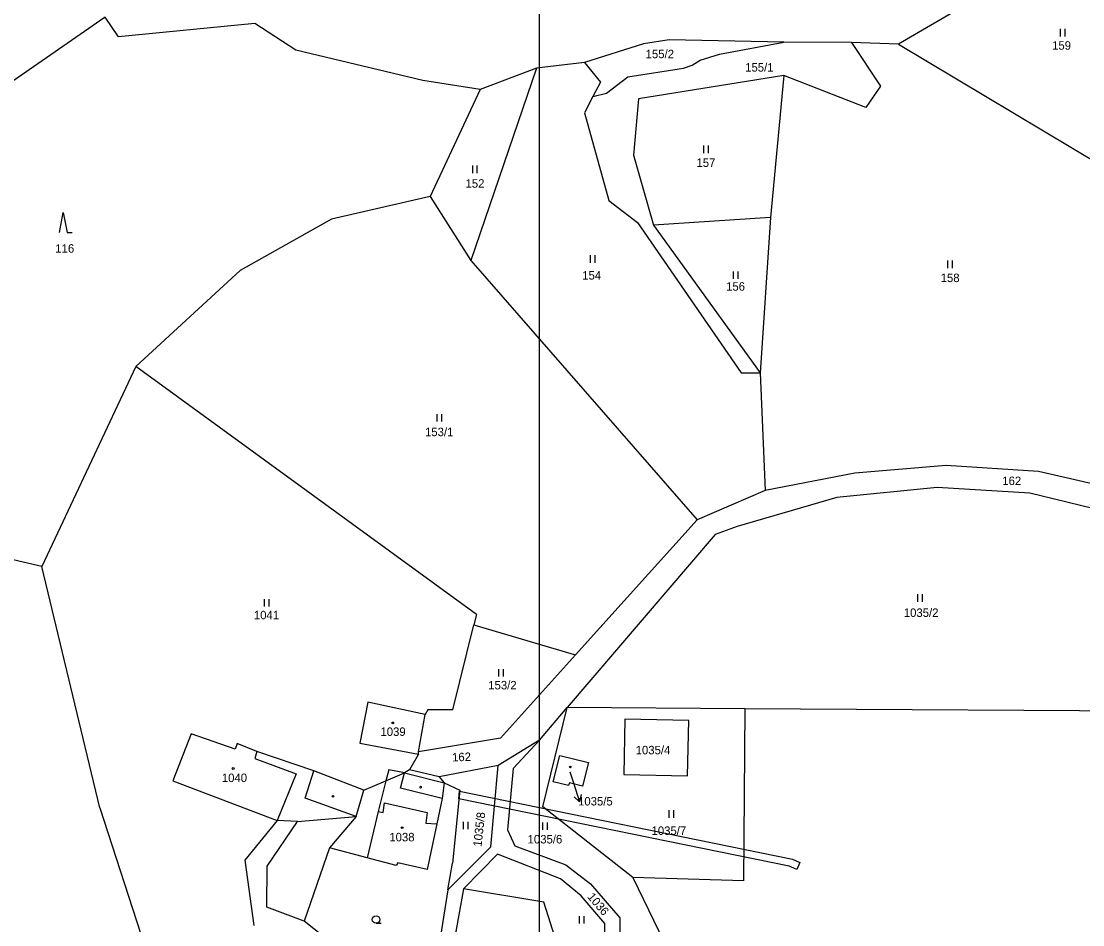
# Model space of a CAD drawing. Extents: x -670359 to -660124, y -978807 to -970072.
# Drawn here: x -670103.9 to -669891.1, y -977465.8 to -977284.7 of the extents above; entities that cross this region are included whole.
import ezdxf

# ---------------------------------------------------------------- set-up
doc = ezdxf.new("R2010")
doc.units = 0
for name, color, linetype in [('Hranice parcel', 7, 'Continuous'), ('ML1000', 7, 'Continuous'), ('Parcelní čísla', 7, 'Continuous'), ('Vnitřní kresba', 7, 'Continuous'), ('Věcná břemena k části', 7, 'Continuous'), ('Značky budov', 7, 'Continuous'), ('Značky kultur', 7, 'Continuous')]:
    doc.layers.add(name, color=color, linetype=linetype)

msp = doc.modelspace()

# ---------------------------------------------------------------- linework, layer by layer
at = {"layer": 'Hranice parcel'}
for p, q in [((-670000.01, -977428.74), (-670005.31, -977434.42)), ((-670009.75, -977450.12), (-670008.29, -977433.88)), ((-670005.31, -977434.42), (-670006.43, -977446.74)), ((-670088.14, -977442.36), (-670079.11, -977470.1)), ((-670006.43, -977446.74), (-670004.98, -977449.96)), ((-670018.36, -977458.79), (-670009.75, -977450.12)), ((-670004.98, -977449.96), (-669994.72, -977453.76)), ((-670008.41, -977451.61), (-670015.27, -977458.55)), ((-669995.83, -977456.55), (-670008.41, -977451.61)), ((-670018.36, -977458.79), (-670017.48, -977453.41)), ((-669994.72, -977453.76), (-669989.76, -977457.53)), ((-669991.65, -977459.94), (-669995.83, -977456.55)), ((-670018.36, -977458.79), (-670022.83, -977486.05)), ((-669989.76, -977457.53), (-669983.91, -977464.41)), ((-669986.93, -977465.5), (-669991.65, -977459.94)), ((-669987.06, -977474.79), (-669986.93, -977465.5)), ((-669983.91, -977464.41), (-669984.06, -977475.2))]:
    msp.add_line(p, q, dxfattribs=at)
for points in [[(-669899.87, -977272.82), (-669928.04, -977289.3)], [(-670087.08, -977283.85), (-670131.79, -977314.81)], [(-670084.43, -977287.79), (-670087.08, -977283.85)], [(-670057.09, -977285.13), (-670084.43, -977287.79)], [(-670048.87, -977290.52), (-670057.09, -977285.13)], [(-669989.31, -977299.81), (-669986.59, -977299.13), (-669982.28, -977295.87), (-669971.16, -977294.1), (-669969.41, -977293.48), (-669967.78, -977292.5), (-669963.95, -977291.28), (-669951.02, -977288.89)], [(-669974.03, -977288.45), (-669979.14, -977289.2)], [(-669951.02, -977288.89), (-669974.03, -977288.45)], [(-669937.48, -977288.95), (-669951.02, -977288.89)], [(-669937.48, -977288.95), (-669931.67, -977297.71)], [(-669928.04, -977289.3), (-669937.48, -977288.95)], [(-670023.39, -977296.58), (-670048.87, -977290.52)], [(-669979.14, -977289.2), (-669991.01, -977292.98)], [(-669928.04, -977289.3), (-669881.51, -977317.07)], [(-669991.01, -977292.98), (-670000.63, -977294.13)], [(-669991.01, -977292.98), (-669987.82, -977296.93)], [(-670000.63, -977294.13), (-670013.78, -977332.64)], [(-670000.63, -977294.13), (-670011.94, -977298.38)], [(-670011.94, -977298.38), (-670023.39, -977296.58)], [(-669987.82, -977296.93), (-669989.31, -977299.81)], [(-669951.04, -977295.59), (-669980.2, -977300.24)], [(-669951.04, -977295.59), (-669953.68, -977324.05)], [(-669934.61, -977301.96), (-669951.04, -977295.59)], [(-670011.94, -977298.38), (-670021.92, -977319.82)], [(-669931.67, -977297.71), (-669934.61, -977301.96)], [(-669989.31, -977299.81), (-669990.98, -977303.02)], [(-669980.2, -977300.24), (-669981.18, -977311.51)], [(-669990.98, -977303.02), (-669986.09, -977320.65)], [(-669981.18, -977311.51), (-669977.19, -977325.55)], [(-670021.92, -977319.82), (-670041.73, -977324.34)], [(-670021.92, -977319.82), (-670013.78, -977332.64)], [(-669986.09, -977320.65), (-669980.39, -977325.01)], [(-670041.73, -977324.34), (-670059.99, -977334.68)], [(-669980.39, -977325.01), (-669959.59, -977355.17)], [(-669953.68, -977324.05), (-669977.19, -977325.55)], [(-669953.68, -977324.05), (-669955.76, -977355.15)], [(-669977.19, -977325.55), (-669955.76, -977355.15)], [(-670013.78, -977332.64), (-669968.39, -977384.63)], [(-670059.99, -977334.68), (-670080.94, -977353.88)], [(-670080.94, -977353.88), (-670099.79, -977393.97)], [(-670012.64, -977403.62), (-670080.94, -977353.88)], [(-669959.59, -977355.17), (-669955.76, -977355.15)], [(-669955.76, -977355.15), (-669954.75, -977378.72)], [(-669918.47, -977373.71), (-669936.77, -977375.26)], [(-669899.99, -977374.96), (-669918.47, -977373.71)], [(-669936.77, -977375.26), (-669954.75, -977378.72)], [(-669884.54, -977378.46), (-669899.99, -977374.96)], [(-669920.28, -977378.11), (-669940.43, -977380.15)], [(-669901.73, -977379.28), (-669920.28, -977378.11)], [(-669954.75, -977378.72), (-669968.39, -977384.63)], [(-669940.43, -977380.15), (-669960.39, -977385.94)], [(-669889.07, -977382.32), (-669901.73, -977379.28)], [(-669968.39, -977384.63), (-669992.8, -977411.69)], [(-669960.39, -977385.94), (-669964.78, -977387.57)], [(-669964.78, -977387.57), (-669994.46, -977422.25)], [(-670099.79, -977393.97), (-670112.18, -977391.09)], [(-670088.14, -977442.36), (-670099.79, -977393.97)], [(-670012.64, -977403.62), (-670013.15, -977405.65)], [(-670017.41, -977422.7), (-670013.15, -977405.65)], [(-670013.15, -977405.65), (-670010.72, -977406.37), (-669993.72, -977411.42), (-669992.8, -977411.69)], [(-670007.85, -977428.37), (-669992.8, -977411.69)], [(-670034.45, -977421.14), (-670036.03, -977429.37)], [(-670022.94, -977423.62), (-670034.45, -977421.14)], [(-670022.38, -977422.67), (-670022.94, -977423.62)], [(-670017.41, -977422.7), (-670022.38, -977422.67)], [(-670000.01, -977428.74), (-669994.46, -977422.25)], [(-669981.31, -977456.31), (-669999.34, -977442.1), (-669994.46, -977422.25)], [(-669958.87, -977422.47), (-669994.46, -977422.25)], [(-669958.87, -977422.47), (-669959.15, -977456.98), (-669981.31, -977456.31)], [(-669869.36, -977423.01), (-669958.87, -977422.47)], [(-670024.28, -977431.13), (-670022.94, -977423.62)], [(-669982.9, -977424.54), (-669983.13, -977435.67)], [(-669970.1, -977424.8), (-669982.9, -977424.54)], [(-669970.33, -977435.94), (-669970.1, -977424.8)], [(-670069.87, -977427.53), (-670073.53, -977436.95)], [(-670061, -977430.56), (-670069.87, -977427.53)], [(-670060.6, -977429.44), (-670061, -977430.56)], [(-670056.69, -977431.07), (-670060.6, -977429.44)], [(-670036.03, -977429.37), (-670024.28, -977431.61)], [(-670007.85, -977428.37), (-670024.28, -977431.13)], [(-670000.01, -977428.74), (-670008.29, -977433.88)], [(-670045.27, -977434.9), (-670056.69, -977431.07)], [(-670024.28, -977431.61), (-670026.06, -977434.72)], [(-670024.28, -977431.61), (-670024.28, -977431.13)], [(-669997.28, -977437.1), (-669995.94, -977431.82)], [(-669995.94, -977431.82), (-669990.21, -977433.27)], [(-669990.21, -977433.27), (-669991.41, -977437.97)], [(-670035.22, -977438.81), (-670045.27, -977434.9)], [(-670030.25, -977434.7), (-670030.81, -977436.93)], [(-670027.11, -977435.35), (-670030.25, -977434.7)], [(-670026.06, -977434.72), (-670027.11, -977435.35)], [(-670020.15, -977436.12), (-670026.06, -977434.72)], [(-670008.29, -977433.88), (-670020.15, -977436.12)], [(-669983.13, -977435.67), (-669970.33, -977435.94)], [(-670073.53, -977436.95), (-670052.62, -977444.85)], [(-670030.81, -977436.93), (-670032.37, -977443.07)], [(-670020.15, -977436.12), (-670019.12, -977437.33)], [(-670019.12, -977437.33), (-670019.54, -977440.44)], [(-670019.12, -977437.33), (-670016.01, -977438.79)], [(-669994.18, -977437.89), (-669997.28, -977437.1)], [(-669994.03, -977437.31), (-669994.18, -977437.89)], [(-669991.41, -977437.97), (-669994.03, -977437.31)], [(-670036.77, -977444.08), (-670035.22, -977438.81)], [(-670016.01, -977438.79), (-670017.48, -977453.41)], [(-670019.54, -977440.44), (-670020.62, -977445.55)], [(-670048.54, -977445.04), (-670036.77, -977444.08)], [(-670032.37, -977443.07), (-670034.59, -977452.33)], [(-670052.62, -977444.85), (-670059.08, -977452.8)], [(-670054.61, -977454.03), (-670048.54, -977445.04)], [(-670048.54, -977445.04), (-670052.62, -977444.85)], [(-670020.62, -977445.55), (-670022.53, -977454.66)], [(-670042.1, -977450.36), (-670047.21, -977465.04)], [(-670034.59, -977452.33), (-670042.1, -977450.36)], [(-670059.08, -977452.8), (-670057.31, -977465.91)], [(-670028.76, -977453.89), (-670034.59, -977452.33)], [(-670054.67, -977462.27), (-670054.61, -977454.03)], [(-670028.44, -977453.34), (-670028.76, -977453.89)], [(-670022.53, -977454.66), (-670028.44, -977453.34)], [(-669981.31, -977456.31), (-669976.1, -977467.06), (-669976.06, -977481.88)], [(-670015.27, -977458.55), (-670020.69, -977488.66)], [(-669999.13, -977461.22), (-670015.27, -977458.55)], [(-669989.82, -977490.72), (-669999.13, -977461.22)], [(-670047.21, -977465.04), (-670054.67, -977462.27)], [(-670037.86, -977472.47), (-670047.21, -977465.04)]]:
    msp.add_lwpolyline(points, dxfattribs=at)
at = {"layer": 'ML1000'}
msp.add_lwpolyline([(-669375, -977000), (-669375, -977500), (-670000, -977500), (-670000, -977000)], close=True, dxfattribs=at)
at = {"layer": 'Parcelní čísla'}
for p, q in [((-669993.91, -977435.1), (-669993.2, -977437.3)), ((-669991.66, -977439.64), (-669991.97, -977441.11))]:
    msp.add_line(p, q, dxfattribs=at)
msp.add_lwpolyline([(-669993.2, -977437.3), (-669991.97, -977441.11), (-669993.09, -977440.1)], dxfattribs=at)
at = {"layer": 'Vnitřní kresba'}
for points in [[(-670056.69, -977431.07), (-670057.1, -977432.42)], [(-670057.1, -977432.42), (-670048.8, -977435.52)], [(-670048.8, -977435.52), (-670052.62, -977444.85)], [(-670046.99, -977440.41), (-670045.27, -977434.9)], [(-670030.81, -977436.93), (-670027.11, -977435.35)], [(-670027.85, -977438.38), (-670027.11, -977435.35)], [(-670027.11, -977435.35), (-670019.12, -977437.33)], [(-670035.22, -977438.81), (-670030.81, -977436.93)], [(-670019.54, -977440.44), (-670027.85, -977438.38)], [(-670036.77, -977444.08), (-670046.99, -977440.41)], [(-670031.33, -977443.24), (-670031.07, -977441.32)], [(-670031.07, -977441.32), (-670022.52, -977443.3)], [(-670036.77, -977444.08), (-670042.1, -977450.36)], [(-670032.37, -977443.07), (-670031.33, -977443.24)], [(-670022.52, -977443.3), (-670022.78, -977445.38)], [(-670022.78, -977445.38), (-670020.62, -977445.55)]]:
    msp.add_lwpolyline(points, dxfattribs=at)
at = {"layer": 'Věcná břemena k části'}
for p, q in [((-670016.18, -977440.52), (-670016.03, -977439.02)), ((-670016.03, -977439.02), (-669949.32, -977452.64)), ((-669949.95, -977454.03), (-670016.18, -977440.52)), ((-669949.32, -977452.64), (-669947.86, -977453.28)), ((-669948.46, -977454.69), (-669949.95, -977454.03)), ((-669947.86, -977453.28), (-669948.46, -977454.69))]:
    msp.add_line(p, q, dxfattribs=at)
at = {"layer": 'Značky budov'}
for centre in [(-670029.44, -977425.32), (-670061.43, -977434.45), (-669993.83, -977434.14), (-670027.55, -977446.3)]:
    msp.add_circle(centre, 0.175, dxfattribs=at)
at = {"layer": 'Značky kultur'}
for p, q in [((-669895.63, -977286.23), (-669895.63, -977287.73)), ((-669894.63, -977287.73), (-669894.63, -977286.23)), ((-669967.17, -977309.63), (-669967.17, -977311.13)), ((-669966.17, -977311.13), (-669966.17, -977309.63)), ((-670013.48, -977313.63), (-670013.48, -977315.13)), ((-670012.48, -977315.13), (-670012.48, -977313.63)), ((-669989.84, -977331.59), (-669989.84, -977333.09)), ((-669988.84, -977333.09), (-669988.84, -977331.59)), ((-669918.24, -977332.67), (-669918.24, -977334.17)), ((-669917.24, -977334.17), (-669917.24, -977332.67)), ((-669961.22, -977334.82), (-669961.22, -977336.32)), ((-669960.22, -977336.32), (-669960.22, -977334.82)), ((-670020.59, -977363.43), (-670020.59, -977364.93)), ((-670019.59, -977364.93), (-670019.59, -977363.43)), ((-669924.21, -977399.53), (-669924.21, -977401.03)), ((-669923.21, -977401.03), (-669923.21, -977399.53)), ((-670055.21, -977400.5), (-670055.21, -977402)), ((-670054.21, -977402), (-670054.21, -977400.5)), ((-670008.24, -977414.54), (-670008.24, -977416.04)), ((-670007.24, -977416.04), (-670007.24, -977414.54)), ((-669974.12, -977442.81), (-669974.12, -977444.31)), ((-669973.12, -977444.31), (-669973.12, -977442.81)), ((-670015.3, -977445.11), (-670015.3, -977446.61)), ((-670014.3, -977446.61), (-670014.3, -977445.11)), ((-669999.43, -977445.27), (-669999.43, -977446.77)), ((-669998.43, -977446.77), (-669998.43, -977445.27)), ((-670032.78, -977465.47), (-670031.78, -977465.47)), ((-669992.05, -977464.04), (-669992.05, -977465.54)), ((-669991.05, -977465.54), (-669991.05, -977464.04))]:
    msp.add_line(p, q, dxfattribs=at)
msp.add_lwpolyline([(-670096.22, -977327.03), (-670095.47, -977323.03), (-670094.72, -977327.03), (-670093.72, -977327.03)], dxfattribs=at)
for centre, radius in [((-670029.44, -977425.32), 0.175), ((-670061.43, -977434.45), 0.175), ((-669993.83, -977434.14), 0.175), ((-670023.84, -977438.19), 0.175), ((-670041.41, -977440.02), 0.175), ((-670027.55, -977446.3), 0.175), ((-670032.78, -977464.72), 0.75)]:
    msp.add_circle(centre, radius, dxfattribs=at)

# ---------------------------------------------------------------- texts
at = {"layer": 'Parcelní čísla'}
for s, height, p in [('159', 1.7, (-669897.26, -977290.4)), ('155/2', 1.7, (-669978.74, -977292.1)), ('155/1', 1.7, (-669958.79, -977294.79)), ('157', 1.7, (-669968.55, -977313.89)), ('152', 1.7, (-670014.85, -977318.06)), ('116', 1.7, (-670097.08, -977331.08)), ('154', 1.7, (-669991.45, -977336.47)), ('158', 1.7, (-669919.6, -977336.97)), ('156', 1.7, (-669962.61, -977338.7)), ('153/1', 1.7, (-670022.97, -977367.85)), ('162', 1.7, (-669907.24, -977377.65)), ('1041', 1.7, (-670057.27, -977404.55)), ('1035/2', 1.7, (-669926.99, -977404.07)), ('153/2', 1.7, (-670010.29, -977418.6)), ('1039', 1.7, (-670031.9, -977427.92)), ('1035/4', 1.7, (-669980.74, -977431.61)), ('1040', 1.7, (-670063.7, -977437.17)), ('1035/5', 0.1, (-669993.91, -977435.1)), ('1035/5', 1.7, (-669992.29, -977441.86)), ('1035/7', 1.7, (-669977.56, -977447.76)), ('1038', 1.7, (-670030.12, -977449.05)), ('1035/6', 1.7, (-670002.4, -977449.47))]:
    msp.add_text(s, height=height, dxfattribs=at).set_placement(p)
for s, rotation, p in [('162', 1.8553, (-670017.52, -977433.05)), ('1035/8', 83.7, (-670011.64, -977450.19)), ('1036', 310.5, (-669990.52, -977460.23))]:
    msp.add_text(s, height=1.7, rotation=rotation, dxfattribs=at).set_placement(p)

doc.saveas('drawing.dxf')
